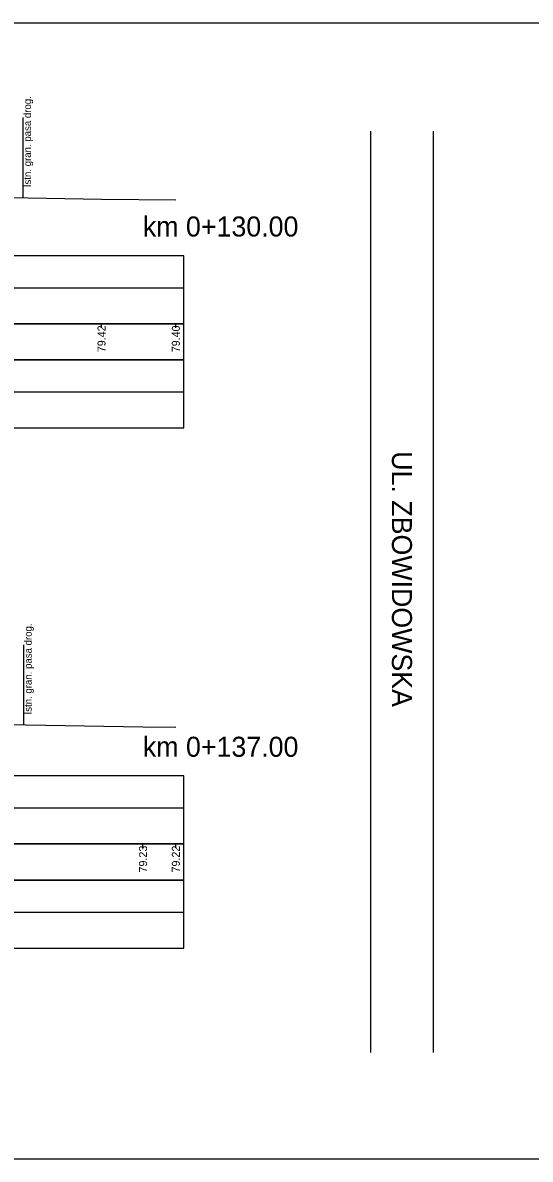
# Model space of a CAD drawing. Extents: x 7492871 to 7493499, y 5802964 to 5802992.
# Drawn here: x 7492974.4 to 7492987.07, y 5802963.88 to 5802992.28 of the extents above; entities that cross this region are included whole.
import ezdxf

# ---------------------------------------------------------------- set-up
doc = ezdxf.new("R2010")
doc.units = 0
for name, color, linetype in [('_wydruk', 7, 'Continuous'), ('opisy_ramki_pop', 7, 'Continuous'), ('pop_granica_istn', 7, 'Continuous'), ('pop_opis', 7, 'Continuous'), ('pop_pikietaz', 7, 'Continuous'), ('pop_teren', 7, 'Continuous')]:
    doc.layers.add(name, color=color, linetype=linetype)

msp = doc.modelspace()

# ---------------------------------------------------------------- linework, layer by layer
at = {"layer": '_wydruk'}
msp.add_lwpolyline([(7492871.369, 5802992.281), (7493499.283, 5802992.281), (7493499.283, 5802963.881), (7492871.369, 5802963.881)], close=True, dxfattribs=at)
at = {"layer": 'opisy_ramki_pop'}
for p, q in [((7492983.082, 5802989.573), (7492983.082, 5802966.547)), ((7492984.648, 5802989.573), (7492984.648, 5802966.547))]:
    msp.add_line(p, q, dxfattribs=at)
at = {"layer": 'pop_granica_istn'}
for p, q in [((7492974.406, 5802988.41), (7492974.406, 5802989.91)), ((7492974.406, 5802987.91), (7492974.406, 5802988.41)), ((7492974.425, 5802975.234), (7492974.425, 5802976.734)), ((7492974.425, 5802974.734), (7492974.425, 5802975.234))]:
    msp.add_line(p, q, dxfattribs=at)
at = {"layer": 'pop_opis'}
for p, q in [((7492964.021, 5802985.659), (7492978.421, 5802985.659)), ((7492964.021, 5802985.659), (7492978.421, 5802985.659)), ((7492964.021, 5802985.659), (7492978.421, 5802985.659)), ((7492964.021, 5802985.659), (7492978.421, 5802985.659)), ((7492976.366, 5802984.659), (7492976.366, 5802984.759)), ((7492978.221, 5802984.659), (7492978.221, 5802984.759)), ((7492964.021, 5802983.059), (7492978.421, 5802983.059)), ((7492964.021, 5802972.659), (7492978.421, 5802972.659)), ((7492964.021, 5802972.659), (7492978.421, 5802972.659)), ((7492964.021, 5802972.659), (7492978.421, 5802972.659)), ((7492964.021, 5802972.659), (7492978.421, 5802972.659)), ((7492977.401, 5802971.659), (7492977.401, 5802971.759)), ((7492978.221, 5802971.659), (7492978.221, 5802971.759)), ((7492964.021, 5802970.059), (7492978.421, 5802970.059))]:
    msp.add_line(p, q, dxfattribs=at)
for points in [[(7492964.021, 5802986.459), (7492964.021, 5802984.759), (7492978.421, 5802984.759), (7492978.421, 5802986.459)], [(7492964.021, 5802986.459), (7492964.021, 5802984.759), (7492978.421, 5802984.759), (7492978.421, 5802986.459)], [(7492964.021, 5802986.459), (7492964.021, 5802984.759), (7492978.421, 5802984.759), (7492978.421, 5802986.459)], [(7492964.021, 5802986.459), (7492964.021, 5802984.759), (7492978.421, 5802984.759), (7492978.421, 5802986.459)], [(7492964.021, 5802984.759), (7492964.021, 5802983.859), (7492978.421, 5802983.859), (7492978.421, 5802984.759)], [(7492964.021, 5802983.859), (7492964.021, 5802982.159), (7492978.421, 5802982.159), (7492978.421, 5802983.859)], [(7492964.021, 5802973.459), (7492964.021, 5802971.759), (7492978.421, 5802971.759), (7492978.421, 5802973.459)], [(7492964.021, 5802973.459), (7492964.021, 5802971.759), (7492978.421, 5802971.759), (7492978.421, 5802973.459)], [(7492964.021, 5802973.459), (7492964.021, 5802971.759), (7492978.421, 5802971.759), (7492978.421, 5802973.459)], [(7492964.021, 5802973.459), (7492964.021, 5802971.759), (7492978.421, 5802971.759), (7492978.421, 5802973.459)], [(7492964.021, 5802971.759), (7492964.021, 5802970.859), (7492978.421, 5802970.859), (7492978.421, 5802971.759)], [(7492964.021, 5802970.859), (7492964.021, 5802969.159), (7492978.421, 5802969.159), (7492978.421, 5802970.859)]]:
    msp.add_lwpolyline(points, close=True, dxfattribs=at)
at = {"layer": 'pop_teren'}
for points in [[(7492964.221, 5802988.072), (7492967.7, 5802987.983), (7492968.594, 5802987.983), (7492968.708, 5802987.972), (7492969.917, 5802987.949), (7492970.203, 5802987.954), (7492970.715, 5802987.956), (7492971.771, 5802987.91), (7492971.895, 5802987.919), (7492972.692, 5802987.942), (7492976.366, 5802987.876), (7492978.221, 5802987.859)], [(7492964.221, 5802974.974), (7492967.563, 5802974.888), (7492968.496, 5802974.888), (7492968.706, 5802974.888), (7492968.736, 5802974.887), (7492970.275, 5802974.854), (7492971.749, 5802974.79), (7492972.004, 5802974.783), (7492972.277, 5802974.776), (7492973.013, 5802974.765), (7492977.401, 5802974.685), (7492978.221, 5802974.678)]]:
    msp.add_lwpolyline(points, dxfattribs=at)

# ---------------------------------------------------------------- texts
at = {"layer": 'pop_granica_istn'}
for p in [(7492974.605, 5802988.171), (7492974.623, 5802974.995)]:
    msp.add_text('Istn. gran. pasa drog.', height=0.18, rotation=90, dxfattribs=at).set_placement(p)
at = {"layer": 'pop_opis'}
for s, p in [('79.42', (7492976.466, 5802984.048)), ('79.40', (7492978.321, 5802984.047)), ('79.23', (7492977.501, 5802971.047)), ('79.22', (7492978.321, 5802971.048))]:
    msp.add_text(s, height=0.2, rotation=90, dxfattribs=at).set_placement(p)
at = {"layer": 'pop_pikietaz'}
for s, p in [('km 0+130.00', (7492977.397, 5802986.939)), ('km 0+137.00', (7492977.397, 5802973.939))]:
    msp.add_text(s, height=0.5, dxfattribs=at).set_placement(p)
msp.add_text('UL. ZBOWIDOWSKA', height=0.5, rotation=270, dxfattribs=at).set_placement((7492983.616, 5802981.573))

doc.saveas('drawing.dxf')
